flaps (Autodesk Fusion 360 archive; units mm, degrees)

design "BRIDGE" references "FLOWER"
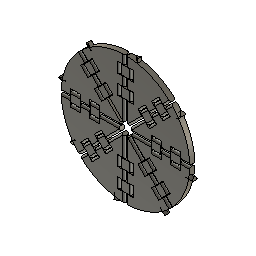
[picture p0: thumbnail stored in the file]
parameter "BRIDGE" = 1.7
parameter "CIRCLEDISTANCE" = 1.7
sketch "Sketch1" plane through (0, 0, 0) normal (0, 1, 0) x axis (1, 0, 0)
  line L1 (0, -50) -> (0, 0)
  line L2 (50, 0) -> (0, 0)
  line L3 (35.3553, -35.3553) -> (0, 0)
  line L4 (49.9224, 0) -> (0, 0)
  line L5 (0.5, -49.9975) -> (0.5, -1.2071)
  line L6 (35, -35.7071) -> (0.5, -1.2071)
  line L7 (4.8, -42.9975) -> (0.5, -42.9975)
  line L8 (4.8, -34.9975) -> (4.8, -42.9975)
  line L9 (0.5, -34.9975) -> (4.8, -34.9975)
  line L10 (4.8, -27.9975) -> (0.5, -27.9975)
  line L11 (4.8, -19.9975) -> (4.8, -27.9975)
  line L12 (0.5, -19.9975) -> (4.8, -19.9975)
  line L13 (27.0097, -33.7979) -> (30.0503, -30.7574)
  line L14 (21.3529, -28.1411) -> (27.0097, -33.7979)
  line L15 (24.3934, -25.1005) -> (21.3529, -28.1411)
  line L16 (16.4031, -23.1913) -> (19.4437, -20.1508)
  line L17 (10.7463, -17.5345) -> (16.4031, -23.1913)
  line L18 (13.7868, -14.4939) -> (10.7463, -17.5345)
  circle C1 centre (0, 0) radius 50
  circle C2 centre (0, 0) radius 5
  point P1 (0, 0)
  point P2 (0, 0)
  point P3 (0, 0)
  point P4 (0, -50)
  point P5 (0, 0)
  point P6 (50, 0)
  point P7 (0, 0)
  point P8 (35.3553, -35.3553)
  point P13 (0.5, -42.9975)
  point P16 (0.5, -34.9975)
  point P17 (0.5, -27.9975)
  point P20 (0.5, -19.9975)
  point P21 (30.0503, -30.7574)
  point P24 (24.3934, -25.1005)
  point P25 (19.4437, -20.1508)
  point P28 (13.7868, -14.4939)
  point P11 (0.5, -49.9975)
  point P12 (35, -35.7071)
  point P18 (4.8, -27.9975)
  point P19 (4.8, -19.9975)
  point P14 (4.8, -42.9975)
  point P15 (4.8, -34.9975)
  point P22 (27.0097, -33.7979)
  point P23 (21.3529, -28.1411)
  point P26 (16.4031, -23.1913)
  point P27 (10.7463, -17.5345)
  coincident P1 P2
  coincident P1 P3
  coincident C1 P4
  vertical L1
  coincident P1 P5
  coincident C1 P6
  perpendicular L1 L2
  horizontal L4
  coincident P1 P7
  coincident C1 P8
  coincident L5 P13
  perpendicular L5 L7
  perpendicular L7 L8
  coincident L5 P16
  perpendicular L5 L9
  coincident L5 P17
  perpendicular L5 L10
  perpendicular L10 L11
  coincident L5 P20
  perpendicular L5 L12
  coincident L6 P21
  perpendicular L6 L13
  perpendicular L13 L14
  coincident L6 P24
  perpendicular L6 L15
  coincident L6 P25
  perpendicular L6 L16
  perpendicular L16 L17
  coincident L6 P28
  perpendicular L6 L18
  concentric C1 C2
  coincident C1 P11
  coincident C1 P12
  dimension "d1" diameter C1 = 100
  dimension "d2" angle L3 L4 = 45
  dimension "d3" = 0.5
  dimension "d4" distance P18 P19 = 8
  dimension "d5" distance P14 P15 = 8 (= "d4")
  dimension "d6" distance P22 P23 = 8 (= "d5")
  dimension "d7" distance P26 P27 = 8 (= "d4")
  dimension "d8" distance P19 P20 = 4.3
  dimension "d9" distance P15 P16 = 4.3 (= "d8")
  dimension "d10" distance P23 P24 = 4.3 (= "d8")
  dimension "d11" distance P27 P28 = 4.3 (= "d8")
  dimension "d13" distance P11 L7 = 7
  dimension "d14" distance L9 L10 = 7
  dimension "d15" distance L15 L16 = 7 (= "d14")
  dimension "d41" diameter C2 = 10
  dimension "d48" distance P12 P21 = 7 (= "d13")
extrude "Extrude1" new body sketch "Sketch1" profile of C1 L5 L6 L7 L8 L9 L10 L11 L12 L13 L14 L15 L16 L17 L18 C2 along normal blind 4
sketch "Sketch2" plane through (0, 0, 19.9975) normal (0, 0, 1) x axis (-1, 0, 0)
  line L1 (-4.8, 0) -> (-0.5, 0)
  line L2 (-4.8, -4) -> (-4.8, 0)
  line L3 (-0.5, -4) -> (-4.8, -4)
  line L4 (-0.5, 0) -> (-0.5, -4)
  line L5 (-2.2, 0) -> (-2.2, -4)
  circle C1 centre (-2.2, -2) radius 0.85
  point P6 (-2.2, -2)
  point P7 (-2.2, -4)
  point P8 (-2.2, 0)
  coincident P6 L5
  midpoint P6 L5
  coincident L3 P7
  coincident L1 P8
  dimension "d21" diameter C1 = 1.7 (= "BRIDGE")
  dimension "d51" distance L4 L5 = 1.7 (= "CIRCLEDISTANCE")
extrude "Extrude2" add sketch "Sketch2" profile of C1 along normal blind 10
sketch "Sketch3" plane through (0, 0, 34.9975) normal (0, 0, 1) x axis (-1, 0, 0)
  line L1 (-4.8, 0) -> (-0.5, 0)
  line L2 (-4.8, -4) -> (-4.8, 0)
  line L3 (-0.5, -4) -> (-4.8, -4)
  line L4 (-0.5, 0) -> (-0.5, -4)
  line L5 (-2.2, 0) -> (-2.2, -4)
  circle C1 centre (-2.2, -2) radius 0.85
  point P8 (-2.2, -2)
  point P6 (-2.2, -4)
  point P7 (-2.2, 0)
  midpoint L5 P8
  coincident L3 P6
  coincident L1 P7
  dimension "d24" diameter C1 = 1.7 (= "BRIDGE")
  dimension "d53" distance L4 L5 = 1.7 (= "CIRCLEDISTANCE")
extrude "Extrude3" add sketch "Sketch3" profile of C1 along normal blind 10
sketch "Sketch4" plane through (14.1404, 0, 14.1404) normal (0.7071, 0, 0.7071) x axis (0, 1, 0)
  line L1 (0, 0.5) -> (0, 4.8)
  line L2 (4, 0.5) -> (0, 0.5)
  line L3 (4, 4.8) -> (4, 0.5)
  line L4 (0, 4.8) -> (4, 4.8)
  line L5 (4, 2.2) -> (0, 2.2)
  circle C1 centre (2, 2.2) radius 0.85
  point P8 (2, 2.2)
  point P6 (0, 2.2)
  point P7 (4, 2.2)
  midpoint L5 P8
  coincident L1 P6
  coincident L3 P7
  dimension "d27" diameter C1 = 1.7 (= "BRIDGE")
  dimension "d54" distance L2 L5 = 1.7 (= "CIRCLEDISTANCE")
extrude "Extrude4" add sketch "Sketch4" profile of C1 along normal blind 10
sketch "Sketch5" plane through (24.747, 0, 24.747) normal (0.7071, 0, 0.7071) x axis (0, 1, 0)
  line L1 (0, 0.5) -> (0, 4.8)
  line L2 (4, 4.8) -> (4, 0.5)
  line L3 (0, 4.8) -> (4, 4.8)
  line L4 (4, 2.2) -> (0, 2.2)
  line L5 (4, 0.5) -> (0, 0.5)
  circle C1 centre (2, 2.2) radius 0.85
  point P8 (2, 2.2)
  point P7 (4, 2.2)
  point P6 (0, 2.2)
  midpoint L4 P8
  coincident L2 P7
  coincident L1 P6
  dimension "d30" diameter C1 = 1.7 (= "BRIDGE")
  dimension "d55" distance L4 L5 = 1.7 (= "CIRCLEDISTANCE")
extrude "Extrude5" add sketch "Sketch5" profile of C1 along normal blind 10
circular_pattern "C-Pattern2" TotalAngle 360
sketch "Sketch8" plane through (0, 0, 0) normal (0, -1, 0) x axis (1, 0, 0)
  line L1 (-16.4031, 23.1913) -> (-19.4437, 20.1508)
  line L2 (-13.7868, 14.4939) -> (-10.7463, 17.5345)
  line L3 (-4.8, 19.9975) -> (-0.5, 19.9975)
  line L4 (-0.5, 27.9975) -> (-4.8, 27.9975)
  line L5 (-4.8, 34.9975) -> (-0.5, 34.9975)
  line L6 (-0.5, 42.9975) -> (-4.8, 42.9975)
  line L7 (-27.0097, 33.7979) -> (-30.0503, 30.7574)
  line L8 (-24.3934, 25.1005) -> (-21.3529, 28.1411)
  line L9 (-4.8, 34.9975) -> (-4.8, 42.9975)
  line L10 (-4.8, 42.9975) -> (-0.5, 42.9975)
  line L11 (-0.5, 34.9975) -> (-4.8, 34.9975)
  line L12 (0.5, 34.9975) -> (4.8, 34.9975)
  line L13 (4.8, 34.9975) -> (4.8, 42.9975)
  line L14 (4.8, 42.9975) -> (0.5, 42.9975)
  line L15 (-4.8, 27.9975) -> (-0.5, 27.9975)
  line L16 (-4.8, 19.9975) -> (-4.8, 27.9975)
  line L17 (-0.5, 19.9975) -> (-4.8, 19.9975)
  line L18 (4.8, 19.9975) -> (4.8, 27.9975)
  line L19 (4.8, 27.9975) -> (0.5, 27.9975)
  line L20 (0.5, 19.9975) -> (4.8, 19.9975)
  line L21 (4.8, 27.9975) -> (-4.8, 27.9975)
  line L22 (4.8, 19.9975) -> (4.8, 27.9975)
  line L23 (-4.8, 19.9975) -> (4.8, 19.9975)
  line L24 (-4.8, 27.9975) -> (-4.8, 19.9975)
  line L25 (4.8, 42.9975) -> (-4.8, 42.9975)
  line L26 (4.8, 34.9975) -> (4.8, 42.9975)
  line L27 (-4.8, 34.9975) -> (4.8, 34.9975)
  line L28 (-4.8, 42.9975) -> (-4.8, 34.9975)
  line L29 (4.4, 35.3975) -> (4.4, 42.5975)
  line L30 (-4.4, 35.3975) -> (4.4, 35.3975)
  line L31 (-4.4, 42.5975) -> (-4.4, 35.3975)
  line L32 (4.4, 42.5975) -> (-4.4, 42.5975)
  line L33 (4.4, 20.3975) -> (4.4, 27.5975)
  line L34 (-4.4, 20.3975) -> (4.4, 20.3975)
  line L35 (-4.4, 27.5975) -> (-4.4, 20.3975)
  line L36 (4.4, 27.5975) -> (-4.4, 27.5975)
  line L37 (-19.4437, 20.1508) -> (-24.3934, 25.1005)
  line L38 (-10.7463, 17.5345) -> (-16.4031, 23.1913)
  line L39 (-3.1643, 3.8714) -> (-13.7868, 14.4939)
  line L40 (-0.5, 19.9975) -> (-0.5, 4.9749)
  line L41 (-4.8, 27.9975) -> (-4.8, 19.9975)
  line L42 (-0.5, 34.9975) -> (-0.5, 27.9975)
  line L43 (-4.8, 42.9975) -> (-4.8, 34.9975)
  line L44 (-0.5, 49.9975) -> (-0.5, 42.9975)
  line L45 (-30.0503, 30.7574) -> (-35, 35.7071)
  line L46 (-21.3529, 28.1411) -> (-27.0097, 33.7979)
  arc A1 centre (0, 0) radius 5 clockwise from (-3.1643, 3.8714) to (-0.5, 4.9749)
  arc A2 centre (0, 0) radius 50 clockwise from (-35, 35.7071) to (-0.5, 49.9975)
  point P36 (4.8, 19.9975)
  point P41 (4.8, 19.9975)
  point P32 (-4.8, 27.9975)
  point P39 (-4.8, 27.9975)
  point P27 (4.8, 34.9975)
  point P45 (4.8, 34.9975)
  point P23 (-4.8, 42.9975)
  point P43 (-4.8, 42.9975)
  horizontal L21
  vertical L22
  horizontal L23
  vertical L24
  coincident P36 P41
  coincident P32 P39
  horizontal L25
  vertical L26
  horizontal L27
  vertical L28
  coincident P27 P45
  coincident P23 P43
  dimension "d66" = 0.4
  dimension "d67" = 0.4 (= "d66")
extrude "Extrude6" new body sketch "Sketch8" profile of L29 L32 L30 L31 L33 L36 L34 L35 against normal blind 4 bodies "hinge"
combine "Combine3"
combine "Combine4"
offset_faces "OffsetFaces1" distance -0.3
circular_pattern "C-Pattern3" TotalAngle 360
fillet "Fillet2" radius 1.5
fillet "Fillet3" radius 1.5 1.5
fillet "Fillet4" radius 1.5 1.5 1.5
fillet "Fillet5" radius 1.5 1.5
work_plane "WorkPlane1" AlongDistance 60
component_insert "Component Insert"
sketch "Sketch9" plane through (0, 0, 60) normal (0, 0, 1) x axis (1, 0, 0)
  line L1 (6.5228, 2.4353) -> (8.9369, 3.8291)
  line L2 (8.9369, 0.1709) -> (6.5228, 1.5646)
  line L3 (9.4428, 3.3938) -> (9.4428, 0.6062)
  curve K1 (35, 2.5) -> (33.9128, 4)
  line L4 (2, 4) -> (33.9128, 4)
  curve K2 (2, 4) -> (0.5, 2.5)
  line L5 (0.5, 1.5) -> (0.5, 2.5)
  curve K3 (0.5, 1.5) -> (2, 0)
  line L6 (2, 0) -> (33.9128, 0)
  curve K4 (33.9128, 0) -> (35, 1.5)
  line L7 (35, 2.5) -> (35, 1.5)
  line L8 (9.4428, 2) -> (0.5, 2)
  arc A1 centre (6.7687, 2) radius 0.5 clockwise from (6.5228, 1.5646) to (6.5228, 2.4353)
  arc A2 centre (8.9469, 0.6708) radius 0.5 clockwise from (9.4428, 0.6062) to (8.9369, 0.1709)
  arc A3 centre (8.9469, 3.3292) radius 0.5 clockwise from (8.9369, 3.8291) to (9.4428, 3.3938)
  point P19 (0.5, 2)
  point P5 (6.7687, 2)
  point P20 (9.4428, 2)
  point P4 (6.5228, 1.5646)
  point P6 (8.9369, 0.1709)
  point P10 (8.9469, 3.3292)
  midpoint L5 P19
  perpendicular L3 L8
  equal L1 L2
  equal L2 L3
  coincident P5 L8
  horizontal L8
  midpoint L3 P20
  dimension "d93" angle L1 L2 = 60
  dimension "d95" angle L1 L3 = 60
  dimension "d96" radius A1 = 0.5
  dimension "d97" radius A3 = 0.5
  dimension "d98" radius A2 = 0.5
  dimension "d99" distance P4 P6 = 2.7876
  dimension "d105" distance P10 L4 = 0.6708
extrude "Extrude7" add sketch "Sketch9" profile of L1 A1 L2 A2 L3 A3 against normal blind 8 and against normal blind 13
offset_faces "OffsetFaces2" distance -0.3
circular_pattern "C-Pattern4" TotalAngle 360 bodies "flap (1)", "flap (2)", "flap (3)", "flap (4)", "flap (5)", "flap (6)", "flap (7)"
named bodies: "flap", "hinge", "flap (1)", "flap (2)", "flap (3)", "flap (4)", "flap (5)", "flap (6)", "flap (7)"

design "FLOWER"
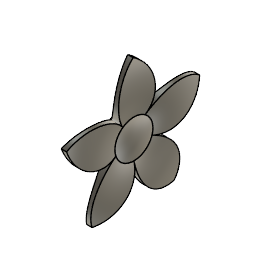
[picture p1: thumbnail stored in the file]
sketch "Sketch1" plane through (0, 0, 0) normal (0, 1, 0) x axis (1, 0, 0)
  line L1 (7, 0) -> (0, 0)
  line L2 (0, -7) -> (0, 0)
  line L3 (1.1383, -8.1383) -> (0, -7)
  line L4 (5.6383, -8.1383) -> (1.1383, -8.1383)
  line L5 (7, -30) -> (7, 0)
  line L6 (5.3071, -30) -> (3.8071, -30)
  arc A1 centre (-18, 0) radius 25 clockwise from (7, 0) to (5.6383, -8.1383)
  arc A2 centre (-33, -18.4864) radius 40 clockwise from (5.6383, -8.1383) to (5.3071, -30)
  arc A3 centre (-14.0996, -21.0923) radius 20 clockwise from (1.1383, -8.1383) to (3.8071, -30)
  point P1 (0, 0)
  point P2 (0, 0)
  point P4 (0, 0)
  point P8 (-18, 0)
  point P9 (5.3071, -30)
  point P12 (3.8071, -30)
  point P3 (7, 0)
  point P5 (0, -7)
  point P6 (1.1383, -8.1383)
  point P7 (5.6383, -8.1383)
  coincident P1 P2
  horizontal L1
  coincident P1 P4
  perpendicular L1 L2
  horizontal L4
  horizontal P1 P8
  tangent A1 L5
  tangent A2 L5
  horizontal P9 P12
  dimension "d1" radius A1 = 25
  dimension "d2" distance P2 P3 = 7
  dimension "d3" distance P4 P5 = 7
  dimension "d5" distance P6 P7 = 4.5
  dimension "d6" angle L2 L3 = 135
  dimension "d7" distance P3 P9 = 30
  dimension "d8" radius A2 = 40
  dimension "d9" radius A3 = 20
  dimension "d10" distance P9 P12 = 1.5
revolve "Revolve1" sketch "Sketch1" AlongAngle 360
revolve "Revolve2" sketch "Sketch1" AlongAngle 360
sketch "Sketch2" plane through (0, 0, 0) normal (1, 0, 0) x axis (0, 1, 0)
  line L1 (0, 30) -> (0, 0)
  line L2 (-4.7836, 6.584) -> (0, 0)
  circle C1 centre (0, 0) radius 30
  circle C2 centre (0, 0) radius 8.1383
  arc A1 centre (8.3194, 16.1039) radius 16.1961 clockwise from (-4.7836, 6.584) to (0, 30)
  arc A2 centre (-8.3194, 16.1039) radius 16.1961 clockwise from (0, 30) to (4.7836, 6.584)
  point P2 (0, 0)
  point P6 (0, 0)
  point P7 (-4.7836, 6.584)
  point P5 (0, 30)
  point P8 (0, 30)
  point P12 (4.7836, 6.584)
  point P11 (0, 30)
  coincident P2 P6
  coincident C2 P7
  coincident P5 P8
  tangent L2 A1
  symmetric L1 P7 P12
  symmetric L1 P8 P11
  symmetric L1 A1 A2
  dimension "d13" angle L1 L2 = 36
extrude "Extrude1" sketch "Sketch2" profile of C2 L1 A1 A2 no distance stored
circular_pattern "C-Pattern1" TotalAngle 360
sketch "Sketch3" plane through (0, 0, 0) normal (-1, 0, 0) x axis (0, -1, 0)
  line L1 (0, 0) -> (0, 3)
  line L2 (0, -3) -> (-4, -3)
  line L3 (0, 3.9282) -> (-4, -3)
  line L4 (0, -3) -> (0, 0)
  line L5 (0, 3.9282) -> (4, -3)
  line L6 (0, -3) -> (4, -3)
  line L7 (0, 4.5282) -> (-4.5196, -3.3)
  line L8 (0, 4.5282) -> (4.5196, -3.3)
  line L9 (0, -3.3) -> (4.5196, -3.3)
  line L10 (0, -3.3) -> (-4.5196, -3.3)
  circle C1 centre (0, 0) radius 7
  point P1 (0, 0)
  point P3 (0, 0)
  point P7 (0, 3)
  point P4 (-4, -3)
  point P9 (4, -3)
  point P5 (0, -3)
  point P11 (0, -3)
  point P6 (0, 3.9282)
  point P10 (0, 3.9282)
  coincident P1 P3
  coincident L1 P7
  perpendicular L2 L4
  equal L1 L4
  vertical L4
  vertical L1
  symmetric L1 P4 P9
  symmetric L1 P5 P11
  symmetric L1 P6 P10
  coincident P6 P10
  dimension "d20" angle L2 L3 = 60
  dimension "d23" distance P4 P5 = 4
  dimension "d24" distance P3 P7 = 3
  dimension "d31" = -0.3
extrude "Extrude2" cut sketch "Sketch3" profile of L2 L3 L5 L6 L7 L8 L9 L10 against normal blind 4
fillet "Fillet1" radius 1
scale "Scale3" ScaleFactor 0.5
offset_faces "OffsetFaces1" distance 0.4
